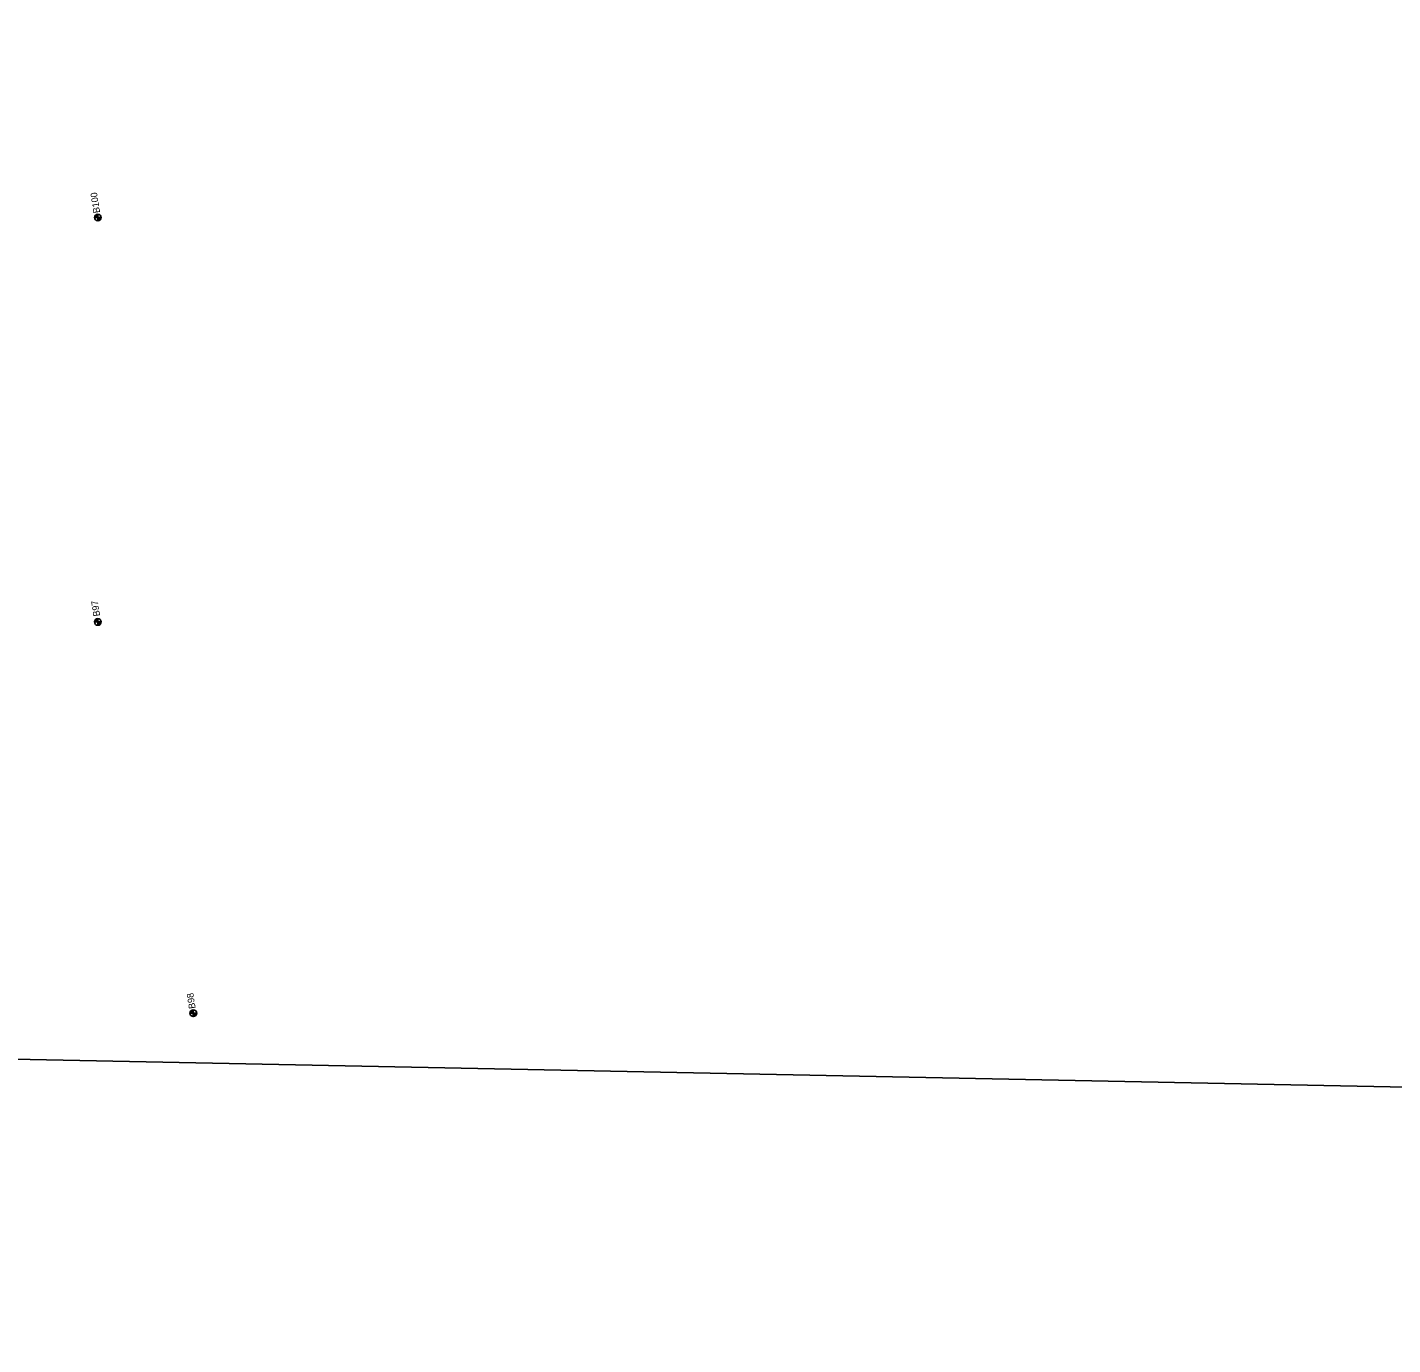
# Model space of a CAD drawing. Extents: x 345549 to 379569, y 127949 to 230467.
# Drawn here: x 355897 to 357938, y 180740 to 182710 of the extents above; entities that cross this region are included whole.
import ezdxf

# ---------------------------------------------------------------- set-up
doc = ezdxf.new("R2010")
doc.units = 0
for name, color, linetype in [('E_SOIL_BORE1 [KAPUR_CADDS_LEVELS]', 7, 'Continuous'), ('E_SOIL_BORE2 [KAPUR_CADDS_LEVELS]', 7, 'Continuous'), ('P_MARK', 7, 'Continuous'), ('P_MISC_NoPlot', 7, 'Continuous'), ('PLT_Sheet_Info', 7, 'Continuous')]:
    doc.layers.add(name, color=color, linetype=linetype)

msp = doc.modelspace()

# ---------------------------------------------------------------- linework, layer by layer
at = {"layer": 'P_MARK'}
for p, q in [((355997.3, 182425.8), (356007.3, 182425.8)), ((356002.3, 182430.8), (356002.3, 182420.8)), ((355997.1, 181821), (356007.1, 181821)), ((356002.1, 181826), (356002.1, 181816)), ((356145, 181241), (356145, 181231)), ((356140, 181236), (356150, 181236))]:
    msp.add_line(p, q, dxfattribs=at)
for centre in [(356002.3, 182425.8), (356002.1, 181821), (356145, 181236)]:
    msp.add_circle(centre, 5, dxfattribs=at)
for centre, radius, start, end in [((356002.3, 182425.8), 4.5, 89.9869, 179.9869), ((356002.3, 182425.8), 4, 89.9869, 179.9869), ((356002.3, 182425.8), 3.5, 89.9869, 179.9869), ((356002.3, 182425.8), 3, 89.9869, 179.9869), ((356002.3, 182425.8), 2.5, 89.9869, 179.9869), ((356002.3, 182425.8), 2, 89.9869, 179.9869), ((356002.3, 182425.8), 1.5, 89.9869, 179.9869), ((356002.3, 182425.8), 1, 89.9869, 179.9869), ((356002.3, 182425.8), 0.5, 89.9869, 179.9869), ((356002.3, 182425.8), 4.5, 269.9869, 359.9869), ((356002.3, 182425.8), 4, 269.9869, 359.9869), ((356002.3, 182425.8), 3.5, 269.9869, 359.9869), ((356002.3, 182425.8), 3, 269.9869, 359.9869), ((356002.3, 182425.8), 2.5, 269.9869, 359.9869), ((356002.3, 182425.8), 2, 269.9869, 359.9869), ((356002.3, 182425.8), 1.5, 269.9869, 359.9869), ((356002.3, 182425.8), 1, 269.9869, 359.9869), ((356002.3, 182425.8), 0.5, 269.9869, 359.9869), ((356002.1, 181821), 4.5, 89.9869, 179.9869), ((356002.1, 181821), 4, 89.9869, 179.9869), ((356002.1, 181821), 3.5, 89.9869, 179.9869), ((356002.1, 181821), 3, 89.9869, 179.9869), ((356002.1, 181821), 2.5, 89.9869, 179.9869), ((356002.1, 181821), 2, 89.9869, 179.9869), ((356002.1, 181821), 1.5, 89.9869, 179.9869), ((356002.1, 181821), 1, 89.9869, 179.9869), ((356002.1, 181821), 0.5, 89.9869, 179.9869), ((356002.1, 181821), 4.5, 269.9869, 359.9869), ((356002.1, 181821), 4, 269.9869, 359.9869), ((356002.1, 181821), 3.5, 269.9869, 359.9869), ((356002.1, 181821), 3, 269.9869, 359.9869), ((356002.1, 181821), 2.5, 269.9869, 359.9869), ((356002.1, 181821), 2, 269.9869, 359.9869), ((356002.1, 181821), 1.5, 269.9869, 359.9869), ((356002.1, 181821), 1, 269.9869, 359.9869), ((356002.1, 181821), 0.5, 269.9869, 359.9869), ((356145, 181236), 4.5, 89.9869, 179.9869), ((356145, 181236), 4, 89.9869, 179.9869), ((356145, 181236), 3.5, 89.9869, 179.9869), ((356145, 181236), 3, 89.9869, 179.9869), ((356145, 181236), 2.5, 89.9869, 179.9869), ((356145, 181236), 2, 89.9869, 179.9869), ((356145, 181236), 1.5, 89.9869, 179.9869), ((356145, 181236), 1, 89.9869, 179.9869), ((356145, 181236), 0.5, 89.9869, 179.9869), ((356145, 181236), 4.5, 269.9869, 359.9869), ((356145, 181236), 4, 269.9869, 359.9869), ((356145, 181236), 3.5, 269.9869, 359.9869), ((356145, 181236), 3, 269.9869, 359.9869), ((356145, 181236), 2.5, 269.9869, 359.9869), ((356145, 181236), 2, 269.9869, 359.9869), ((356145, 181236), 1.5, 269.9869, 359.9869), ((356145, 181236), 1, 269.9869, 359.9869), ((356145, 181236), 0.5, 269.9869, 359.9869)]:
    msp.add_arc(centre, radius, start, end, dxfattribs=at)
at = {"layer": 'P_MISC_NoPlot'}
msp.add_lwpolyline([(347086.9, 181344.4), (347770.4, 215283.3), (369368.8, 214831.3), (369344.6, 213590.3), (376989.6, 213459.5), (376331, 180755.4)], close=True, dxfattribs=at)
at = {"layer": 'PLT_Sheet_Info'}
msp.add_line((377080.8, 180740.3), (347086.9, 181344.4), dxfattribs=at)

# ---------------------------------------------------------------- texts
at = {"layer": 'E_SOIL_BORE1 [KAPUR_CADDS_LEVELS]'}
for s, p in [('B97', (356005.7, 181830.2)), ('B98', (356148.5, 181243.4))]:
    msp.add_text(s, height=10, rotation=98.957, dxfattribs=at).set_placement(p)
at = {"layer": 'E_SOIL_BORE2 [KAPUR_CADDS_LEVELS]'}
msp.add_text('B100', height=10, rotation=98.957, dxfattribs=at).set_placement((356005.7, 182433.2))

doc.saveas('drawing.dxf')
